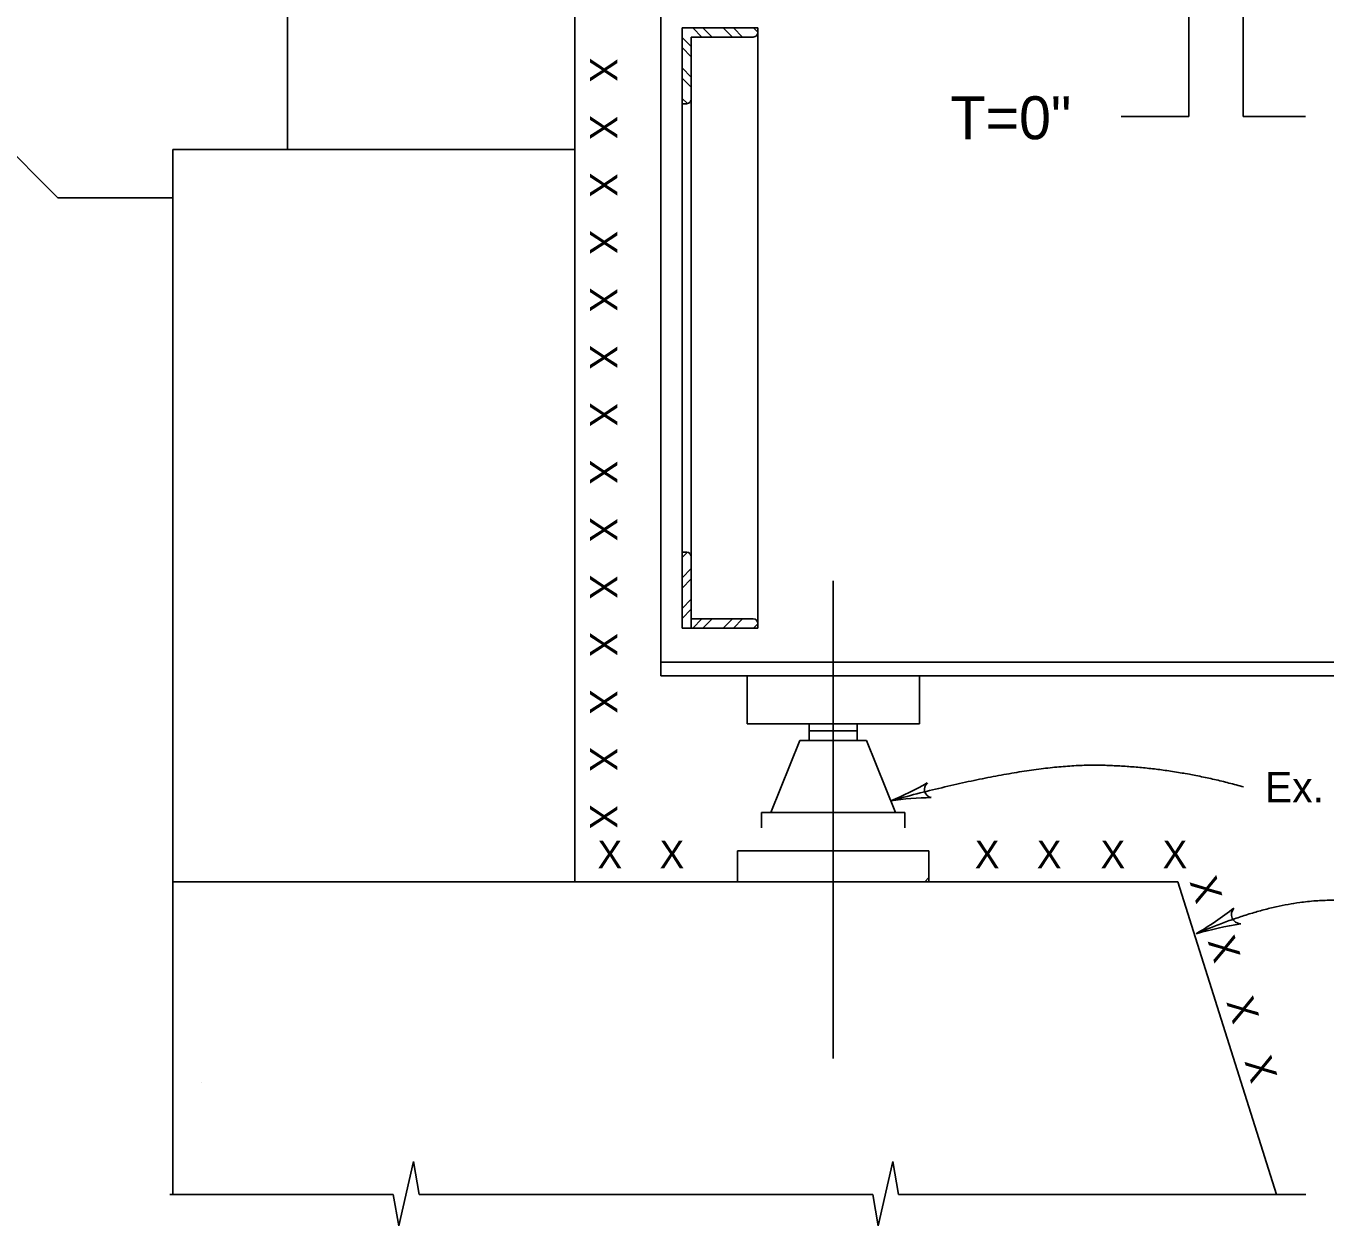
# Model space of a CAD drawing. Extents: x -706 to 14950, y -1867 to 6417.
# Drawn here: x 454 to 613.1, y -1349.7 to -1202.9 of the extents above; entities that cross this region are included whole.
import ezdxf

# ---------------------------------------------------------------- set-up
doc = ezdxf.new("R2010")
doc.units = 0
for name, color, linetype in [('Level 42', 7, 'Continuous'), ('Level 43', 7, 'Continuous'), ('Level 44', 7, 'Continuous'), ('Level 47', 7, 'Continuous')]:
    doc.layers.add(name, color=color, linetype=linetype)

msp = doc.modelspace()

# ---------------------------------------------------------------- linework, layer by layer
at = {"layer": 'Level 42'}
for p, q in [((486.08, -1218), (486.08, -1171.85)), ((521.23, -1174.58), (521.23, -1218)), ((457.95, -1223.91), (447.27, -1213.22)), ((472.01, -1218), (486.08, -1218)), ((472.01, -1218), (472.01, -1223.91)), ((472.01, -1218.53), (472.01, -1218.53)), ((472.01, -1221.04), (472.01, -1221.04)), ((472.01, -1223.91), (457.95, -1223.91)), ((552.87, -1270.78), (552.87, -1329.26)), ((541.15, -1303.81), (541.16, -1303.81)), ((564.08, -1307.61), (564.58, -1307.11))]:
    msp.add_line(p, q, dxfattribs=at)
at = {"layer": 'Level 43'}
for p, q in [((531.77, -1198.1), (531.77, -1282.41)), ((534.36, -1203.1), (534.36, -1276.56)), ((534.36, -1203.1), (543.64, -1203.1)), ((536.79, -1204.23), (535.67, -1203.1)), ((538.04, -1204.23), (536.92, -1203.1)), ((540.52, -1204.23), (539.39, -1203.1)), ((541.77, -1204.23), (540.65, -1203.1)), ((543.64, -1203.62), (543.12, -1203.1)), ((543.64, -1203.1), (543.64, -1203.67)), ((543.64, -1203.1), (543.64, -1276.05)), ((535.48, -1205.4), (534.36, -1204.27)), ((535.48, -1204.23), (535.48, -1211.83)), ((535.48, -1204.23), (543.08, -1204.23)), ((535.48, -1206.64), (534.36, -1205.52)), ((535.48, -1209.13), (534.36, -1208.01)), ((535.48, -1210.38), (534.36, -1209.25)), ((535.01, -1212.38), (534.36, -1211.73)), ((534.36, -1212.39), (534.93, -1212.39)), ((535.48, -1211.83), (535.48, -1276.56)), ((486.08, -1218.01), (521.23, -1218.01)), ((521.23, -1218), (521.23, -1307.61)), ((472.01, -1345.89), (472.01, -1223.91)), ((535.01, -1267.28), (534.36, -1267.93)), ((534.36, -1267.28), (534.93, -1267.28)), ((535.48, -1275.44), (535.48, -1267.85)), ((535.48, -1269.29), (534.36, -1270.42)), ((535.48, -1270.53), (534.36, -1271.66)), ((535.48, -1273.02), (534.36, -1274.15)), ((535.48, -1274.26), (534.36, -1275.39)), ((534.36, -1276.56), (543.64, -1276.56)), ((535.48, -1275.44), (543.08, -1275.44)), ((536.79, -1275.44), (535.67, -1276.56)), ((538.04, -1275.44), (536.92, -1276.56)), ((540.52, -1275.44), (539.39, -1276.56)), ((541.77, -1275.44), (540.65, -1276.56)), ((543.64, -1276.05), (543.12, -1276.56)), ((543.64, -1276.56), (543.64, -1276)), ((531.77, -1280.73), (707.26, -1280.73)), ((531.77, -1282.41), (707.26, -1282.41)), ((542.32, -1282.41), (563.42, -1282.41)), ((542.32, -1282.41), (542.32, -1288.28)), ((563.42, -1282.41), (563.42, -1288.28)), ((542.32, -1288.28), (563.42, -1288.28)), ((549.93, -1288.28), (549.93, -1290.33)), ((549.93, -1289.15), (555.8, -1289.15)), ((555.8, -1288.28), (555.8, -1290.33)), ((545.24, -1299.12), (548.77, -1290.33)), ((548.77, -1290.33), (556.96, -1290.33)), ((556.96, -1290.33), (560.48, -1299.12)), ((544.08, -1299.12), (561.65, -1299.12)), ((544.08, -1299.12), (544.08, -1301.01)), ((561.65, -1299.12), (561.65, -1301.01)), ((541.15, -1303.81), (541.15, -1307.61)), ((541.15, -1303.81), (564.58, -1303.81)), ((564.58, -1303.81), (564.58, -1307.61)), ((521.23, -1307.61), (472.01, -1307.61)), ((521.23, -1307.61), (595.06, -1307.61)), ((595.06, -1307.61), (607.14, -1345.89))]:
    msp.add_line(p, q, dxfattribs=at)
for centre, start_param, end_param in [((543.08, -1203.66), 3.141593, 4.712389), ((534.92, -1211.82), 3.141593, 4.712389), ((534.92, -1267.84), 4.712389, 6.283185), ((543.08, -1276), 4.712389, 6.283185)]:
    msp.add_ellipse(centre, major_axis=(0, 0.563), ratio=0.999779, start_param=start_param, end_param=end_param, dxfattribs=at)
at = {"layer": 'Level 44'}
for p, q in [((602.75, -1312.75), (602.76, -1312.75)), ((499.67, -1349.74), (501.49, -1341.83)), ((501.49, -1341.83), (502.19, -1345.89)), ((558.36, -1349.74), (560.17, -1341.83)), ((560.17, -1341.83), (560.88, -1345.89)), ((499.01, -1345.89), (471.67, -1345.89)), ((499.01, -1345.89), (499.67, -1349.74)), ((557.7, -1345.89), (502.19, -1345.89)), ((557.7, -1345.89), (558.36, -1349.74)), ((610.72, -1345.89), (560.88, -1345.89))]:
    msp.add_line(p, q, dxfattribs=at)
for centre, start, end in [((576.42, -1278.22), 300.2676, 308.0221), ((609.08, -1353.67), 98.7879, 106.5423)]:
    msp.add_arc(centre, 41.4, start, end, dxfattribs=at)
for centre, major_axis, ratio, start_param, end_param in [((603.01, -1311.5), (-1.29, -0.56), 0.873734, 5.258637, 7.300638), ((474.35, -1320.91), (0, 11.31), 0.999779, 3.245854, 3.24606)]:
    msp.add_ellipse(centre, major_axis=major_axis, ratio=ratio, start_param=start_param, end_param=end_param, dxfattribs=at)
msp.add_open_spline([(597.3, -1313.98), (606.24, -1310.1), (619.74, -1309.68), (620.58, -1310.95)], degree=2, dxfattribs=at)
at = {"layer": 'Level 47'}
for p, q in [((596.42, -1171.85), (596.42, -1213.97)), ((603.04, -1179.26), (603.04, -1213.97)), ((596.42, -1213.97), (588.1, -1213.97)), ((603.04, -1213.97), (610.68, -1213.97)), ((535.48, -1266.42), (535.48, -1265.72)), ((564.87, -1297.31), (564.87, -1297.31))]:
    msp.add_line(p, q, dxfattribs=at)
for centre, start, end in [((546.1, -1263.58), 292.0372, 299.7916), ((565.23, -1334.11), 90.5574, 98.3119)]:
    msp.add_arc(centre, 36.8, start, end, dxfattribs=at)
msp.add_ellipse((565.26, -1296.24), major_axis=(-1.2, -0.33), ratio=0.873734, start_param=5.258637, end_param=7.300638, dxfattribs=at)
msp.add_open_spline([(559.91, -1297.69), (576.61, -1293.16), (594.41, -1293.53), (603.1, -1296.01)], degree=2, dxfattribs=at)

# ---------------------------------------------------------------- texts
at = {"layer": 'Level 44'}
for rotation, p in [(270, (523.08, -1206.76)), (270, (523.08, -1213.79)), (270, (523.08, -1220.82)), (270, (523.08, -1227.85)), (270, (523.08, -1234.88)), (270, (523.08, -1241.91)), (270, (523.08, -1248.94)), (270, (523.08, -1255.98)), (270, (523.08, -1263.01)), (270, (523.08, -1270.04)), (270, (523.08, -1277.07)), (270, (523.08, -1284.1)), (270, (523.08, -1291.13)), (270, (523.08, -1298.16)), (287, (596.47, -1307.58)), (287, (598.69, -1314.84)), (287, (600.97, -1322.3)), (287, (603.19, -1329.56))]:
    msp.add_text('X', height=3.37, rotation=rotation, dxfattribs=at).set_placement(p)
for s, height, p in [('T=0"', 5.25, (567.23, -1216.73)), ('Ex. rocker', 3.75, (605.71, -1297.91)), ('X', 3.37, (524.02, -1305.95)), ('X', 3.37, (531.62, -1305.95)), ('X', 3.37, (570.21, -1305.95)), ('X', 3.37, (577.8, -1305.95)), ('X', 3.37, (585.6, -1305.95)), ('X', 3.37, (593.2, -1305.95))]:
    msp.add_text(s, height=height, dxfattribs=at).set_placement(p)

doc.saveas('drawing.dxf')
